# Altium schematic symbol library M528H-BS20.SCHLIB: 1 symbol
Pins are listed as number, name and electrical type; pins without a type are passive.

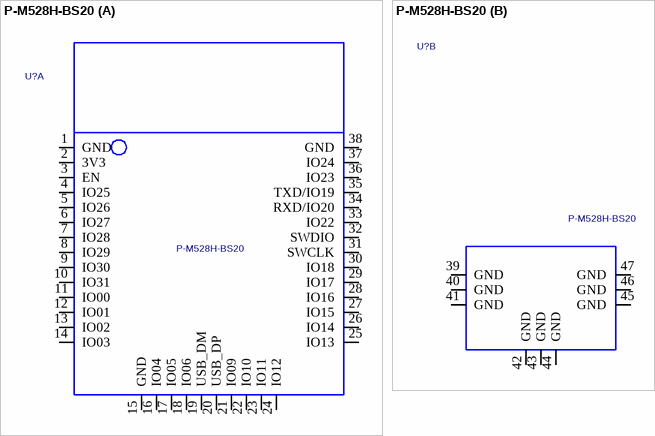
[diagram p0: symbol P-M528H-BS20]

## P-M528H-BS20
designator U?
footprint P-M528H-BS20
part A pins: 1 GND, 2 3V3, 3 EN, 4 IO25, 5 IO26, 6 IO27, 7 IO28, 8 IO29, 9 IO30, 10 IO31, 11 IO00, 12 IO01, 13 IO02, 14 IO03, 15 GND, 16 IO04, 17 IO05, 18 IO06, 19 USB_DM, 20 USB_DP, 21 IO09, 22 IO10, 23 IO11, 24 IO12, 25 IO13, 26 IO14, 27 IO15, 28 IO16, 29 IO17, 30 IO18, 31 SWCLK, 32 SWDIO, 33 IO22, 34 RXD/IO20, 35 TXD/IO19, 36 IO23, 37 IO24, 38 GND
part B pins: 39 GND, 40 GND, 41 GND, 42 GND, 43 GND, 44 GND, 45 GND, 46 GND, 47 GND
